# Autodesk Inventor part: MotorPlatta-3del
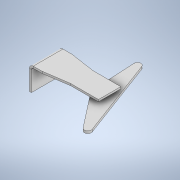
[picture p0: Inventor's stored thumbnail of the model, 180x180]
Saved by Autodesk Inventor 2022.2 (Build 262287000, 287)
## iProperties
Created: 2022-03
Part Number: MotorPlatta-3del
Material: Generic
Document SubType Name: Sheet Metal
Designer: cl
Density: 1 g/cm^3
Sheet Metal Rule: Default
Appearance: Default
Author: cl
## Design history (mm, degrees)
node "Face1"
  sketch "Sketch1"
    geometry: L1 (0, 0)-(0, -186); L2 (0, -186)-(-80, -186); L3 (-80, -186)-(-235, -163); L4 (-235, -163)-(-410, -163); L5 (-410, -163)-(-410, -23); L6 (-410, -23)-(-235, -23); L7 (-235, -23)-(-80, 0); L8 (-80, 0)-(0, 0)
    constraints: 16 end point, 3 perpendicular, 1 horizontal, 1 parallel, 1 vertical
    dimensions: "d0" = 186 distance of L1.start L1.end; "d1" = 80 distance of L1.end L2.end; "d2" = 175 distance of L3.end L4.end; "d3" = 140 distance of L4.end L5.end; "d4" = 23 distance between parallel lines of L2 L4; "d5" = 80 distance from line of L1 L7.end; "d6" = 410 distance between parallel lines of L1 L5; "d7" = 175 distance of L5.end L6.end
node "Flange1"
sketch "Sketch3"
  geometry: L1 (235, -163)-(410, -163) reference; L2 (410, -163)-(410, -23) reference; C1 r 15 at (318, -93); 1 further point
  constraints: 1 centre point
  dimensions: "d19" = 30 diameter of C1; "d20" = 70 distance from line of L1 C1.centre; "d21" = 92 distance from line of L2 C1.centre
extrude "Extrusion1" join sketch "Sketch3" distance "d22" = 28; taper "d23" = 0 deg
sketch "Sketch4"
  geometry: L1 (-318, 93)-(-318, -93) reference; L2 (-18.068, 6.756)-(-33.012, -278.383); L3 (-18.068, 6.756)-(157.721, 231.756); L4 (7.629, -286.837)-(193.94, 211.473); L5 (-18.068, 6.756)-(100.785, -37.682); C1 r 15 at (0, 0) reference; A1 r 21 centre (-12.041, -279.482) between (-33.012, -278.383) and (7.629, -286.837); A2 r 21 centre (174.27, 218.827) between (193.94, 211.473) and (157.721, 231.756)
  constraints: 8 end point, 4 point on circle, 4 tangent, 2 centre point, 1 midpoint, 1 perpendicular, 1 point on line
  dimensions: "d39" = 3 deg angle of L1 L2; "d40" = 21 radius of A1; "d42" = 21 radius of A2; "d43" = 532 distance of A2.centre A1.centre; "d44" = 266 distance of L4.end L5.end (= d45); "d45" = 266 distance of L4.start L5.end (derived); "d46" = 145 deg angle of L2 L3; "d47" = 19.29 distance of L2.start C1.centre
extrude "Extrusion2" join sketch "Sketch4" distance "d29" = 15; taper "d30" = 0 deg
sketch "Sketch6"
  geometry: C1 r 6 at (174.27, 218.827); C2 r 6 at (-12.041, -279.482); A1 r 21 centre (174.27, 218.827) between (193.94, 211.473) and (157.721, 231.756) reference; A2 r 21 centre (-12.041, -279.482) between (-33.012, -278.383) and (7.629, -286.837) reference; 1 further point
  constraints: 2 centre point, 2 coincident
  dimensions: "d48" = 12 diameter of C1; "d49" = 12 diameter of C2
extrude "Extrusion4" join sketch "Sketch6" distance "d50" = 10; taper "d51" = 0 deg
body "Solid1"
face "Plate1" dims "d8" = 12 (= Thickness)
sketch "Sketch2"
  geometry: L1 through (0, 93) direction (0, -1); L2 through (75, 0) direction (1, 0); L3 (150, 0)-(150, 186); L4 (150, 186)-(0, 186)
  constraints: 6 end point, 1 horizontal, 1 perpendicular, 1 vertical
face "Plate2" dims "d8" = 12 (= Thickness), "d9" = 12 (= BendReliefWidth), "d10" = 6 (= BendReliefDepth), "d11" = 24 (= MinimumRemnant), "d12" = 12 (= TransitionRadius), "d13" = 150, "d14" = 90 deg, "d15" = 12 (= BendRadius), "d16" = 48 (= CornerReliefSize), "d17" = 12 (= GapSize), "d18" = 12 (= JacobiRadiusSize), "SeamGap" = 0.01
bend "Bend1" dims "d8" = 12 (= Thickness), "d9" = 12 (= BendReliefWidth), "d10" = 6 (= BendReliefDepth), "d11" = 24 (= MinimumRemnant), "d12" = 12 (= TransitionRadius), "d13" = 150, "d14" = 90 deg, "d15" = 12 (= BendRadius), "SeamGap" = 0.01
feature "Corner1" dims "d13" = 150, "d14" = 90 deg, "d16" = 48 (= CornerReliefSize), "d17" = 12 (= GapSize), "d18" = 12 (= JacobiRadiusSize)
other parameters: "Thickness" = 12 (derived), "KFactor" = 4.4, "BendRadius" = 12 (= Thickness), "BendReliefWidth" = 12 (= Thickness), "BendReliefDepth" = 6 (= 0.5 x Thickness), "CornerReliefSize" = 48 (= 4 x Thickness), "MinimumRemnant" = 24 (= 2 x Thickness), "TransitionRadius" = 12 (= BendRadius), "JacobiRadiusSize" = 12 (= BendRadius), "GapSize" = 12 (= Thickness)
